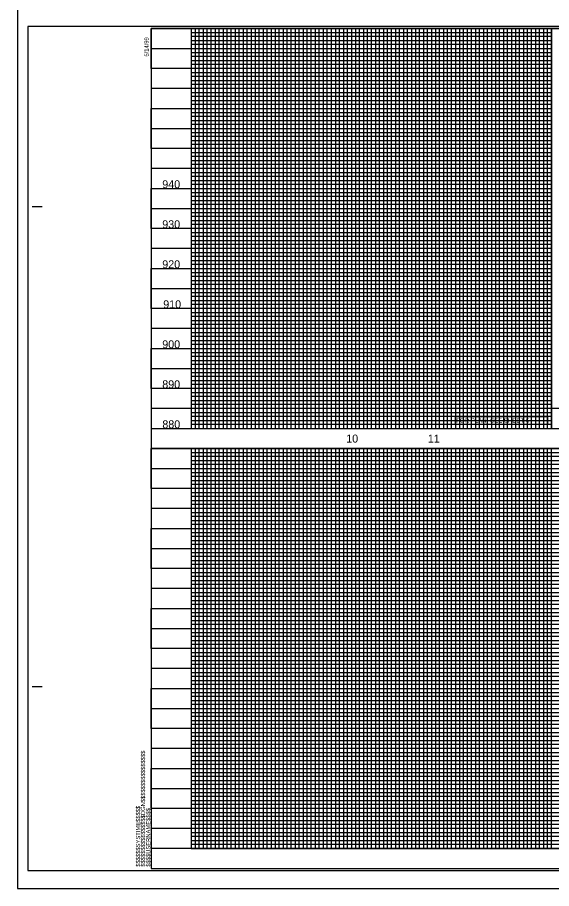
# Model space of a CAD drawing. Extents: x 1967929 to 1975641, y 546296 to 568534.
# Drawn here: x 1969864 to 1970531, y 564134 to 565223 of the extents above; entities that cross this region are included whole.
import ezdxf

# ---------------------------------------------------------------- set-up
doc = ezdxf.new("R2010")
doc.units = 0
for name, color, linetype in [('Exist Vertical Profile Horizontal Axis Label Major', 7, 'Continuous'), ('Exist Vertical Profile Vertical Axis Label', 7, 'Continuous'), ('Old_Level_41', 7, 'Continuous'), ('Old_Level_43', 7, 'Continuous'), ('Old_Level_46', 7, 'Continuous'), ('Prop Grid Mask', 7, 'Continuous'), ('Scratch_Level_3', 7, 'Continuous'), ('Sheet Cutting Line CELL', 7, 'Continuous'), ('Sheet Plot Border Inside CELL', 7, 'Continuous'), ('Sheet Plot Border Outside CELL', 7, 'Continuous'), ('Sheet Profile CELL', 7, 'Continuous'), ('Sheet Profile Grid Major CELL', 7, 'Continuous'), ('Sheet Profile Grid Middle CELL', 7, 'Continuous'), ('Sheet Profile Grid Minor CELL', 7, 'Continuous')]:
    doc.layers.add(name, color=color, linetype=linetype)

msp = doc.modelspace()

# ---------------------------------------------------------------- linework, layer by layer
at = {"layer": 'Old_Level_41'}
for p, q in [((1969882.9, 564986.4), (1969895.4, 564986.4)), ((1969882.9, 564386.4), (1969895.4, 564386.4))]:
    msp.add_line(p, q, dxfattribs=at)
at = {"layer": 'Old_Level_43'}
for p, q in [((1970081.4, 565198.9), (1970081.4, 565198.9)), ((1970081.4, 564573.9), (1970081.4, 564573.9))]:
    msp.add_line(p, q, dxfattribs=at)
at = {"layer": 'Old_Level_46'}
for p, q in [((1970031.4, 565208.9), (1970031.4, 565208.9)), ((1970031.4, 564583.9), (1970031.4, 564583.9))]:
    msp.add_line(p, q, dxfattribs=at)
at = {"layer": 'Prop Grid Mask'}
msp.add_lwpolyline([(1970411.5, 564723.9), (1970526.4, 564723.9), (1970526.4, 564713.9), (1970411.5, 564713.9)], close=True, dxfattribs=at)
at = {"layer": 'Scratch_Level_3'}
for points in [[(1970081.4, 565208.9), (1970081.4, 564708.9), (1971481.4, 564708.9), (1971481.4, 565012.5), (1971331.4, 565012.5), (1971331.4, 565208.9)], [(1970081.4, 565208.9), (1970081.4, 564708.9), (1971331.4, 564708.9), (1971331.4, 564977.2), (1971331.4, 564977.2), (1971331.4, 565208.9)], [(1970081.4, 564683.9), (1970081.4, 564183.9), (1971481.4, 564183.9), (1971481.4, 564683.9)], [(1970081.4, 564683.9), (1970081.4, 564183.9), (1971381.4, 564183.9), (1971381.4, 564683.9)], [(1970081.4, 564683.9), (1970081.4, 564183.9), (1971481.4, 564183.9), (1971481.4, 564683.9)]]:
    msp.add_lwpolyline(points, close=True, dxfattribs=at)
at = {"layer": 'Sheet Cutting Line CELL'}
msp.add_line((1969864.4, 565233.9), (1969864.4, 564133.9), dxfattribs=at)
at = {"layer": 'Sheet Plot Border Inside CELL'}
msp.add_lwpolyline([(1969877.4, 564156.3), (1971543.9, 564156.3), (1971543.9, 565211.4), (1969877.4, 565211.4)], close=True, dxfattribs=at)
at = {"layer": 'Sheet Plot Border Outside CELL'}
msp.add_lwpolyline([(1969864.4, 564133.9), (1971548.4, 564133.9), (1971548.4, 565233.9), (1969864.4, 565233.9)], close=True, dxfattribs=at)
at = {"layer": 'Sheet Profile CELL'}
for p, q in [((1970031.4, 564708.9), (1971531.4, 564708.9)), ((1971531.4, 564683.9), (1970031.4, 564683.9)), ((1971531.4, 564183.9), (1970031.4, 564183.9))]:
    msp.add_line(p, q, dxfattribs=at)
msp.add_lwpolyline([(1971531.4, 565208.9), (1970031.4, 565208.9), (1970031.4, 564158.9), (1971531.4, 564158.9)], close=True, dxfattribs=at)
at = {"layer": 'Sheet Profile Grid Major CELL'}
for points in [[(1970531.3, 565158.9), (1970031.4, 565158.9), (1970031.4, 565208.9), (1971331.4, 565208.9)], [(1970081.4, 565208.9), (1970081.4, 564708.9), (1970131.4, 564708.9), (1970131.4, 565208.9)], [(1970181.4, 565208.9), (1970181.4, 564708.9), (1970231.4, 564708.9), (1970231.4, 565208.9)], [(1970281.4, 565208.9), (1970281.4, 564708.9), (1970331.4, 564708.9), (1970331.4, 565208.9)], [(1970381.4, 565208.9), (1970381.4, 564708.9), (1970431.4, 564708.9), (1970431.4, 565208.9)], [(1970481.4, 565208.9), (1970481.4, 564708.9), (1970531.4, 564708.9), (1970531.4, 565208.9)], [(1970531.4, 565208.9), (1970531.4, 564708.9), (1970581.4, 564708.9), (1970581.4, 565208.9)], [(1970531.3, 565058.9), (1970031.4, 565058.9), (1970031.4, 565108.9), (1970531.3, 565108.9)], [(1970531.3, 564958.9), (1970031.4, 564958.9), (1970031.4, 565008.9), (1970531.3, 565008.9)], [(1970531.3, 564858.9), (1970031.4, 564858.9), (1970031.4, 564908.9), (1970531.3, 564908.9)], [(1970531.3, 564758.9), (1970031.4, 564758.9), (1970031.4, 564808.9), (1970531.3, 564808.9)], [(1971531.4, 564633.9), (1970031.4, 564633.9), (1970031.4, 564683.9), (1971531.4, 564683.9)], [(1970081.4, 564683.9), (1970081.4, 564183.9), (1970131.4, 564183.9), (1970131.4, 564683.9)], [(1970181.4, 564683.9), (1970181.4, 564183.9), (1970231.4, 564183.9), (1970231.4, 564683.9)], [(1970281.4, 564683.9), (1970281.4, 564183.9), (1970331.4, 564183.9), (1970331.4, 564683.9)], [(1970381.4, 564683.9), (1970381.4, 564183.9), (1970431.4, 564183.9), (1970431.4, 564683.9)], [(1970481.4, 564683.9), (1970481.4, 564183.9), (1970531.4, 564183.9), (1970531.4, 564683.9)], [(1971531.4, 564533.9), (1970031.4, 564533.9), (1970031.4, 564583.9), (1971531.4, 564583.9)], [(1971531.4, 564433.9), (1970031.4, 564433.9), (1970031.4, 564483.9), (1971531.4, 564483.9)], [(1971531.4, 564333.9), (1970031.4, 564333.9), (1970031.4, 564383.9), (1971531.4, 564383.9)], [(1971531.4, 564233.9), (1970031.4, 564233.9), (1970031.4, 564283.9), (1971531.4, 564283.9)]]:
    msp.add_lwpolyline(points, dxfattribs=at)
at = {"layer": 'Sheet Profile Grid Middle CELL'}
for points in [[(1970031.4, 565208.9), (1970031.4, 565183.9), (1970531.3, 565183.9)], [(1970106.4, 564708.9), (1970106.4, 565208.9)], [(1970156.4, 565208.9), (1970156.4, 564708.9), (1970206.4, 564708.9), (1970206.4, 565208.9)], [(1970256.4, 565208.9), (1970256.4, 564708.9), (1970306.4, 564708.9), (1970306.4, 565208.9)], [(1970356.4, 565208.9), (1970356.4, 564708.9), (1970406.4, 564708.9), (1970406.4, 565208.9)], [(1970456.4, 565208.9), (1970456.4, 564708.9), (1970506.4, 564708.9), (1970506.4, 565208.9)], [(1970531.3, 565133.9), (1970031.4, 565133.9), (1970031.4, 565083.9), (1970531.3, 565083.9)], [(1970531.3, 565033.9), (1970031.4, 565033.9), (1970031.4, 564983.9), (1970531.3, 564983.9)], [(1970531.3, 564933.9), (1970031.4, 564933.9), (1970031.4, 564883.9), (1970531.3, 564883.9)], [(1970531.3, 564833.9), (1970031.4, 564833.9), (1970031.4, 564783.9), (1970531.3, 564783.9)], [(1970531.3, 564733.9), (1970031.4, 564733.9)], [(1970581.4, 564733.9), (1970531.4, 564733.9)], [(1970031.4, 564683.9), (1970031.4, 564658.9), (1971531.4, 564658.9)], [(1970106.4, 564183.9), (1970106.4, 564683.9)], [(1970156.4, 564683.9), (1970156.4, 564183.9), (1970206.4, 564183.9), (1970206.4, 564683.9)], [(1970256.4, 564683.9), (1970256.4, 564183.9), (1970306.4, 564183.9), (1970306.4, 564683.9)], [(1970356.4, 564683.9), (1970356.4, 564183.9), (1970406.4, 564183.9), (1970406.4, 564683.9)], [(1970456.4, 564683.9), (1970456.4, 564183.9), (1970506.4, 564183.9), (1970506.4, 564683.9)], [(1971531.4, 564608.9), (1970031.4, 564608.9), (1970031.4, 564558.9), (1971531.4, 564558.9)], [(1971531.4, 564508.9), (1970031.4, 564508.9), (1970031.4, 564458.9), (1971531.4, 564458.9)], [(1971531.4, 564408.9), (1970031.4, 564408.9), (1970031.4, 564358.9), (1971531.4, 564358.9)], [(1971531.4, 564308.9), (1970031.4, 564308.9), (1970031.4, 564258.9), (1971531.4, 564258.9)], [(1971531.4, 564208.9), (1970031.4, 564208.9)]]:
    msp.add_lwpolyline(points, dxfattribs=at)
at = {"layer": 'Sheet Profile Grid Minor CELL'}
for p, q in [((1970531.3, 564723.9), (1970081.4, 564723.9)), ((1970081.4, 564723.9), (1970081.4, 564718.9)), ((1970081.4, 564718.9), (1970531.3, 564718.9))]:
    msp.add_line(p, q, dxfattribs=at)
for points in [[(1970086.4, 565208.9), (1970086.4, 564708.9), (1970091.4, 564708.9), (1970091.4, 565208.9)], [(1970096.4, 565208.9), (1970096.4, 564708.9), (1970101.4, 564708.9), (1970101.4, 565208.9)], [(1970111.4, 565208.9), (1970111.4, 564708.9), (1970116.4, 564708.9), (1970116.4, 565208.9)], [(1970121.4, 565208.9), (1970121.4, 564708.9), (1970126.4, 564708.9), (1970126.4, 565208.9)], [(1970136.4, 565208.9), (1970136.4, 564708.9), (1970141.4, 564708.9), (1970141.4, 565208.9)], [(1970146.4, 565208.9), (1970146.4, 564708.9), (1970151.4, 564708.9), (1970151.4, 565208.9)], [(1970161.4, 565208.9), (1970161.4, 564708.9), (1970166.4, 564708.9), (1970166.4, 565208.9)], [(1970171.4, 565208.9), (1970171.4, 564708.9), (1970176.4, 564708.9), (1970176.4, 565208.9)], [(1970186.4, 565208.9), (1970186.4, 564708.9), (1970191.4, 564708.9), (1970191.4, 565208.9)], [(1970196.4, 565208.9), (1970196.4, 564708.9), (1970201.4, 564708.9), (1970201.4, 565208.9)], [(1970211.4, 565208.9), (1970211.4, 564708.9), (1970216.4, 564708.9), (1970216.4, 565208.9)], [(1970221.4, 565208.9), (1970221.4, 564708.9), (1970226.4, 564708.9), (1970226.4, 565208.9)], [(1970236.4, 565208.9), (1970236.4, 564708.9), (1970241.4, 564708.9), (1970241.4, 565208.9)], [(1970246.4, 564708.9), (1970251.4, 564708.9), (1970251.4, 565208.9)], [(1970246.4, 565208.9), (1970246.4, 564708.9)], [(1970261.4, 565208.9), (1970261.4, 564708.9), (1970266.4, 564708.9), (1970266.4, 565208.9)], [(1970271.4, 565208.9), (1970271.4, 564708.9), (1970276.4, 564708.9), (1970276.4, 565208.9)], [(1970286.4, 565208.9), (1970286.4, 564708.9), (1970291.4, 564708.9), (1970291.4, 565208.9)], [(1970296.4, 565208.9), (1970296.4, 564708.9), (1970301.4, 564708.9), (1970301.4, 565208.9)], [(1970311.4, 565208.9), (1970311.4, 564708.9), (1970316.4, 564708.9), (1970316.4, 565208.9)], [(1970321.4, 565208.9), (1970321.4, 564708.9), (1970326.4, 564708.9), (1970326.4, 565208.9)], [(1970336.4, 565208.9), (1970336.4, 564708.9), (1970341.4, 564708.9), (1970341.4, 565208.9)], [(1970346.4, 565208.9), (1970346.4, 564708.9), (1970351.4, 564708.9), (1970351.4, 565208.9)], [(1970361.4, 565208.9), (1970361.4, 564708.9), (1970366.4, 564708.9), (1970366.4, 565208.9)], [(1970371.4, 565208.9), (1970371.4, 564708.9), (1970376.4, 564708.9), (1970376.4, 565208.9)], [(1970386.4, 565208.9), (1970386.4, 564708.9), (1970391.4, 564708.9), (1970391.4, 565208.9)], [(1970396.4, 565208.9), (1970396.4, 564708.9), (1970401.4, 564708.9), (1970401.4, 565208.9)], [(1970411.4, 565208.9), (1970411.4, 564708.9), (1970426.4, 564708.9), (1970426.4, 565208.9)], [(1970416.4, 565208.9), (1970416.4, 564708.9), (1970421.4, 564708.9), (1970421.4, 565208.9)], [(1970436.4, 565208.9), (1970436.4, 564708.9), (1970441.4, 564708.9), (1970441.4, 565208.9)], [(1970446.4, 565208.9), (1970446.4, 564708.9), (1970451.4, 564708.9), (1970451.4, 565208.9)], [(1970461.4, 565208.9), (1970461.4, 564708.9), (1970466.4, 564708.9), (1970466.4, 565208.9)], [(1970471.4, 565208.9), (1970471.4, 564708.9), (1970476.4, 564708.9), (1970476.4, 565208.9)], [(1970486.4, 565208.9), (1970486.4, 564708.9), (1970491.4, 564708.9), (1970491.4, 565208.9)], [(1970496.4, 565208.9), (1970496.4, 564708.9), (1970501.4, 564708.9), (1970501.4, 565208.9)], [(1970511.4, 565208.9), (1970511.4, 564708.9), (1970516.4, 564708.9), (1970516.4, 565208.9)], [(1970521.4, 565208.9), (1970521.4, 564708.9), (1970526.4, 564708.9), (1970526.4, 565208.9)], [(1970081.4, 565203.9), (1970531.3, 565203.9)], [(1970531.4, 565198.9), (1970081.4, 565198.9), (1970081.4, 565193.9), (1970531.4, 565193.9)], [(1970531.4, 565188.9), (1970081.4, 565188.9), (1970081.4, 565178.9), (1970531.4, 565178.9)], [(1970531.3, 565173.9), (1970081.4, 565173.9), (1970081.4, 565168.9), (1970531.3, 565168.9)], [(1970531.3, 565163.9), (1970081.4, 565163.9), (1970081.4, 565153.9), (1970531.3, 565153.9)], [(1970531.4, 565148.9), (1970081.4, 565148.9), (1970081.4, 565143.9), (1970531.3, 565143.9)], [(1970531.3, 565138.9), (1970081.4, 565138.9), (1970081.4, 565128.9), (1970531.3, 565128.9)], [(1970531.3, 565123.9), (1970081.4, 565123.9), (1970081.4, 565118.9), (1970531.4, 565118.9)], [(1970531.3, 565113.9), (1970081.4, 565113.9), (1970081.4, 565103.9), (1970531.3, 565103.9)], [(1970531.3, 565098.9), (1970081.4, 565098.9), (1970081.4, 565093.9), (1970531.3, 565093.9)], [(1970531.3, 565088.9), (1970081.4, 565088.9), (1970081.4, 565078.9), (1970531.3, 565078.9)], [(1970531.3, 565073.9), (1970081.4, 565073.9), (1970081.4, 565068.9), (1970531.3, 565068.9)], [(1970531.3, 565063.9), (1970081.4, 565063.9), (1970081.4, 565053.9), (1970531.3, 565053.9)], [(1970531.3, 565048.9), (1970081.4, 565048.9), (1970081.4, 565043.9), (1970531.3, 565043.9)], [(1970531.3, 565038.9), (1970081.4, 565038.9), (1970081.4, 565028.9), (1970531.3, 565028.9)], [(1970531.3, 565023.9), (1970081.4, 565023.9), (1970081.4, 565018.9), (1970531.4, 565018.9)], [(1970531.3, 565013.9), (1970081.4, 565013.9), (1970081.4, 565003.9), (1970531.3, 565003.9)], [(1970531.4, 564998.9), (1970081.4, 564998.9), (1970081.4, 564993.9), (1970531.3, 564993.9)], [(1970531.3, 564988.9), (1970081.4, 564988.9), (1970081.4, 564978.9), (1970531.3, 564978.9)], [(1970531.3, 564973.9), (1970081.4, 564973.9), (1970081.4, 564968.9), (1970531.3, 564968.9)], [(1970531.3, 564963.9), (1970081.4, 564963.9), (1970081.4, 564953.9), (1970531.3, 564953.9)], [(1970531.3, 564948.9), (1970081.4, 564948.9), (1970081.4, 564943.9), (1970531.3, 564943.9)], [(1970531.3, 564938.9), (1970081.4, 564938.9), (1970081.4, 564928.9), (1970531.3, 564928.9)], [(1970531.4, 564923.9), (1970081.4, 564923.9), (1970081.4, 564918.9), (1970531.3, 564918.9)], [(1970531.3, 564913.9), (1970081.4, 564913.9)], [(1970081.4, 564903.9), (1970531.3, 564903.9)], [(1970531.3, 564898.9), (1970081.4, 564898.9), (1970081.4, 564893.9), (1970531.3, 564893.9)], [(1970531.3, 564888.9), (1970081.4, 564888.9)], [(1970081.4, 564878.9), (1970531.3, 564878.9)], [(1970531.3, 564873.9), (1970081.4, 564873.9), (1970081.4, 564868.9), (1970531.3, 564868.9)], [(1970531.3, 564863.9), (1970081.4, 564863.9), (1970081.4, 564853.9), (1970531.3, 564853.9)], [(1970531.4, 564848.9), (1970081.4, 564848.9), (1970081.4, 564843.9), (1970531.3, 564843.9)], [(1970531.4, 564838.9), (1970081.4, 564838.9), (1970081.4, 564828.9), (1970531.3, 564828.9)], [(1970531.3, 564823.9), (1970081.4, 564823.9), (1970081.4, 564818.9), (1970531.3, 564818.9)], [(1970531.3, 564813.9), (1970081.4, 564813.9), (1970081.4, 564803.9), (1970531.3, 564803.9)], [(1970531.3, 564798.9), (1970081.4, 564798.9), (1970081.4, 564793.9), (1970531.3, 564793.9)], [(1970531.3, 564788.9), (1970081.4, 564788.9), (1970081.4, 564778.9), (1970531.3, 564778.9)], [(1970531.3, 564773.9), (1970081.4, 564773.9), (1970081.4, 564768.9), (1970531.3, 564768.9)], [(1970531.3, 564763.9), (1970081.4, 564763.9), (1970081.4, 564753.9), (1970531.3, 564753.9)], [(1970531.3, 564748.9), (1970081.4, 564748.9), (1970081.4, 564743.9), (1970531.3, 564743.9)], [(1970531.3, 564738.9), (1970081.4, 564738.9), (1970081.4, 564728.9), (1970531.3, 564728.9)], [(1970531.3, 564713.9), (1970081.4, 564713.9), (1970081.4, 564708.9), (1971481.4, 564708.9)], [(1970086.4, 564683.9), (1970086.4, 564183.9), (1970091.4, 564183.9), (1970091.4, 564683.9)], [(1970096.4, 564683.9), (1970096.4, 564183.9), (1970101.4, 564183.9), (1970101.4, 564683.9)], [(1970111.4, 564683.9), (1970111.4, 564183.9), (1970116.4, 564183.9), (1970116.4, 564683.9)], [(1970121.4, 564683.9), (1970121.4, 564183.9), (1970126.4, 564183.9), (1970126.4, 564683.9)], [(1970136.4, 564683.9), (1970136.4, 564183.9), (1970141.4, 564183.9), (1970141.4, 564683.9)], [(1970146.4, 564683.9), (1970146.4, 564183.9), (1970151.4, 564183.9), (1970151.4, 564683.9)], [(1970161.4, 564683.9), (1970161.4, 564183.9), (1970166.4, 564183.9), (1970166.4, 564683.9)], [(1970171.4, 564683.9), (1970171.4, 564183.9), (1970176.4, 564183.9), (1970176.4, 564683.9)], [(1970186.4, 564683.9), (1970186.4, 564183.9), (1970191.4, 564183.9), (1970191.4, 564683.9)], [(1970196.4, 564683.9), (1970196.4, 564183.9), (1970201.4, 564183.9), (1970201.4, 564683.9)], [(1970211.4, 564683.9), (1970211.4, 564183.9), (1970216.4, 564183.9), (1970216.4, 564683.9)], [(1970221.4, 564683.9), (1970221.4, 564183.9), (1970226.4, 564183.9), (1970226.4, 564683.9)], [(1970236.4, 564683.9), (1970236.4, 564183.9), (1970241.4, 564183.9), (1970241.4, 564683.9)], [(1970246.4, 564183.9), (1970251.4, 564183.9), (1970251.4, 564683.9)], [(1970246.4, 564683.9), (1970246.4, 564183.9)], [(1970261.4, 564683.9), (1970261.4, 564183.9), (1970266.4, 564183.9), (1970266.4, 564683.9)], [(1970271.4, 564683.9), (1970271.4, 564183.9), (1970276.4, 564183.9), (1970276.4, 564683.9)], [(1970286.4, 564683.9), (1970286.4, 564183.9), (1970291.4, 564183.9), (1970291.4, 564683.9)], [(1970296.4, 564683.9), (1970296.4, 564183.9), (1970301.4, 564183.9), (1970301.4, 564683.9)], [(1970311.4, 564683.9), (1970311.4, 564183.9), (1970316.4, 564183.9), (1970316.4, 564683.9)], [(1970321.4, 564683.9), (1970321.4, 564183.9), (1970326.4, 564183.9), (1970326.4, 564683.9)], [(1970336.4, 564683.9), (1970336.4, 564183.9), (1970341.4, 564183.9), (1970341.4, 564683.9)], [(1970346.4, 564683.9), (1970346.4, 564183.9), (1970351.4, 564183.9), (1970351.4, 564683.9)], [(1970361.4, 564683.9), (1970361.4, 564183.9), (1970366.4, 564183.9), (1970366.4, 564683.9)], [(1970371.4, 564683.9), (1970371.4, 564183.9), (1970376.4, 564183.9), (1970376.4, 564683.9)], [(1970386.4, 564683.9), (1970386.4, 564183.9), (1970391.4, 564183.9), (1970391.4, 564683.9)], [(1970396.4, 564683.9), (1970396.4, 564183.9), (1970401.4, 564183.9), (1970401.4, 564683.9)], [(1970411.4, 564683.9), (1970411.4, 564183.9), (1970426.4, 564183.9), (1970426.4, 564683.9)], [(1970416.4, 564683.9), (1970416.4, 564183.9), (1970421.4, 564183.9), (1970421.4, 564683.9)], [(1970436.4, 564683.9), (1970436.4, 564183.9), (1970441.4, 564183.9), (1970441.4, 564683.9)], [(1970446.4, 564683.9), (1970446.4, 564183.9), (1970451.4, 564183.9), (1970451.4, 564683.9)], [(1970461.4, 564683.9), (1970461.4, 564183.9), (1970466.4, 564183.9), (1970466.4, 564683.9)], [(1970471.4, 564683.9), (1970471.4, 564183.9), (1970476.4, 564183.9), (1970476.4, 564683.9)], [(1970486.4, 564683.9), (1970486.4, 564183.9), (1970491.4, 564183.9), (1970491.4, 564683.9)], [(1970496.4, 564683.9), (1970496.4, 564183.9), (1970501.4, 564183.9), (1970501.4, 564683.9)], [(1970511.4, 564683.9), (1970511.4, 564183.9), (1970516.4, 564183.9), (1970516.4, 564683.9)], [(1970521.4, 564683.9), (1970521.4, 564183.9), (1970526.4, 564183.9), (1970526.4, 564683.9)], [(1970081.4, 564678.9), (1971481.4, 564678.9)], [(1971481.4, 564673.9), (1970081.4, 564673.9), (1970081.4, 564668.9), (1971481.4, 564668.9)], [(1971481.4, 564663.9), (1970081.4, 564663.9), (1970081.4, 564653.9), (1971481.4, 564653.9)], [(1971481.4, 564648.9), (1970081.4, 564648.9), (1970081.4, 564643.9), (1971481.4, 564643.9)], [(1971481.4, 564638.9), (1970081.4, 564638.9), (1970081.4, 564628.9), (1971481.4, 564628.9)], [(1971481.4, 564623.9), (1970081.4, 564623.9), (1970081.4, 564618.9), (1971481.4, 564618.9)], [(1971481.4, 564613.9), (1970081.4, 564613.9), (1970081.4, 564603.9), (1971481.4, 564603.9)], [(1971481.4, 564598.9), (1970081.4, 564598.9), (1970081.4, 564593.9), (1971481.4, 564593.9)], [(1971481.4, 564588.9), (1970081.4, 564588.9), (1970081.4, 564578.9), (1971481.4, 564578.9)], [(1971481.4, 564573.9), (1970081.4, 564573.9), (1970081.4, 564568.9), (1971481.4, 564568.9)], [(1971481.4, 564563.9), (1970081.4, 564563.9), (1970081.4, 564553.9), (1971481.4, 564553.9)], [(1971481.4, 564548.9), (1970081.4, 564548.9), (1970081.4, 564543.9), (1971481.4, 564543.9)], [(1971481.4, 564538.9), (1970081.4, 564538.9), (1970081.4, 564528.9), (1971481.4, 564528.9)], [(1971481.4, 564523.9), (1970081.4, 564523.9), (1970081.4, 564518.9), (1971481.4, 564518.9)], [(1971481.4, 564513.9), (1970081.4, 564513.9), (1970081.4, 564503.9), (1971481.4, 564503.9)], [(1971481.4, 564498.9), (1970081.4, 564498.9), (1970081.4, 564493.9), (1971481.4, 564493.9)], [(1971481.4, 564488.9), (1970081.4, 564488.9), (1970081.4, 564478.9), (1971481.4, 564478.9)], [(1971481.4, 564473.9), (1970081.4, 564473.9), (1970081.4, 564468.9), (1971481.4, 564468.9)], [(1971481.4, 564463.9), (1970081.4, 564463.9), (1970081.4, 564453.9), (1971481.4, 564453.9)], [(1971481.4, 564448.9), (1970081.4, 564448.9), (1970081.4, 564443.9), (1971481.4, 564443.9)], [(1971481.4, 564438.9), (1970081.4, 564438.9), (1970081.4, 564428.9), (1971481.4, 564428.9)], [(1971481.4, 564423.9), (1970081.4, 564423.9), (1970081.4, 564418.9), (1971481.4, 564418.9)], [(1971481.4, 564413.9), (1970081.4, 564413.9), (1970081.4, 564403.9), (1971481.4, 564403.9)], [(1971481.4, 564398.9), (1970081.4, 564398.9), (1970081.4, 564393.9), (1971481.4, 564393.9)], [(1971481.4, 564388.9), (1970081.4, 564388.9)], [(1970081.4, 564378.9), (1971481.4, 564378.9)], [(1971481.4, 564373.9), (1970081.4, 564373.9), (1970081.4, 564368.9), (1971481.4, 564368.9)], [(1971481.4, 564363.9), (1970081.4, 564363.9)], [(1970081.4, 564353.9), (1971481.4, 564353.9)], [(1971481.4, 564348.9), (1970081.4, 564348.9), (1970081.4, 564343.9), (1971481.4, 564343.9)], [(1971481.4, 564338.9), (1970081.4, 564338.9), (1970081.4, 564328.9), (1971481.4, 564328.9)], [(1971481.4, 564323.9), (1970081.4, 564323.9), (1970081.4, 564318.9), (1971481.4, 564318.9)], [(1971481.4, 564313.9), (1970081.4, 564313.9), (1970081.4, 564303.9), (1971481.4, 564303.9)], [(1971481.4, 564298.9), (1970081.4, 564298.9), (1970081.4, 564293.9), (1971481.4, 564293.9)], [(1971481.4, 564288.9), (1970081.4, 564288.9), (1970081.4, 564278.9), (1971481.4, 564278.9)], [(1971481.4, 564273.9), (1970081.4, 564273.9), (1970081.4, 564268.9), (1971481.4, 564268.9)], [(1971481.4, 564263.9), (1970081.4, 564263.9), (1970081.4, 564253.9), (1971481.4, 564253.9)], [(1971481.4, 564248.9), (1970081.4, 564248.9), (1970081.4, 564243.9), (1971481.4, 564243.9)], [(1971481.4, 564238.9), (1970081.4, 564238.9), (1970081.4, 564228.9), (1971481.4, 564228.9)], [(1971481.4, 564223.9), (1970081.4, 564223.9), (1970081.4, 564218.9), (1971481.4, 564218.9)], [(1971481.4, 564213.9), (1970081.4, 564213.9), (1970081.4, 564203.9), (1971481.4, 564203.9)], [(1971481.4, 564198.9), (1970081.4, 564198.9), (1970081.4, 564193.9), (1971481.4, 564193.9)], [(1971481.4, 564188.9), (1970081.4, 564188.9), (1970081.4, 564183.9), (1971481.4, 564183.9)]]:
    msp.add_lwpolyline(points, dxfattribs=at)

# ---------------------------------------------------------------- texts
at = {"layer": 'Exist Vertical Profile Horizontal Axis Label Major'}
for s, p in [('10', (1970275, 564691.3)), ('11', (1970376.9, 564691.3))]:
    msp.add_text(s, height=10, dxfattribs=at).set_placement(p)
at = {"layer": 'Exist Vertical Profile Vertical Axis Label'}
for s, p in [('940', (1970045.3, 565009.1)), ('930', (1970045.3, 564959.1)), ('920', (1970045.3, 564909.1)), ('910', (1970046.5, 564859.1)), ('900', (1970045.3, 564809.1)), ('890', (1970045.3, 564759.1)), ('880', (1970045.4, 564709.1))]:
    msp.add_text(s, height=10, dxfattribs=at).set_placement(p)
at = {"layer": 'Prop Grid Mask'}
msp.add_text('FOR PLAN: SEE SHEET 6', height=5.493, dxfattribs=at).set_placement((1970412.4, 564716.2))
at = {"layer": 'Sheet Profile CELL'}
for s, p in [('5/14/99', (1970028.2, 565173.7)), ('$$$$$$$$$$$$$$$$DGN$$$$$$$$$$$$$$$$', (1970023.8, 564161.2)), ('$$$$$$SYSTIME$$$$$', (1970017.7, 564161.2)), ('$$$$USERNAME$$$$', (1970030.4, 564161.2))]:
    msp.add_text(s, height=5.25, rotation=90, dxfattribs=at).set_placement(p)

doc.saveas('drawing.dxf')
